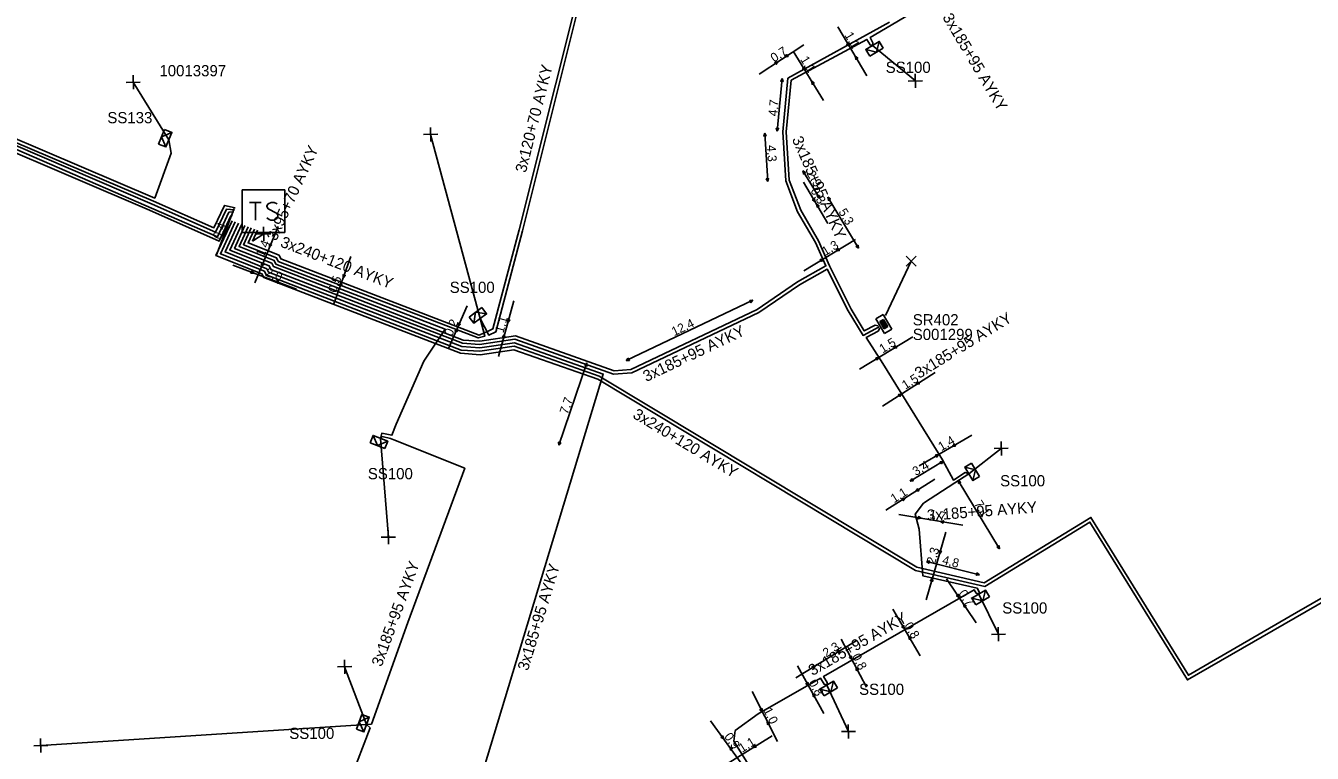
# Model space of a CAD drawing. Extents: x -762500 to -761285, y -1155006 to -1154135.
# Drawn here: x -762023.9 to -761909.8, y -1154863.6 to -1154799 of the extents above; entities that cross this region are included whole.
import ezdxf

# ---------------------------------------------------------------- set-up
doc = ezdxf.new("R2010")
doc.units = 0
for name, color, linetype in [('Vrstva 25', 7, 'Continuous'), ('Vrstva 26', 7, 'Continuous'), ('Vrstva 28', 7, 'Continuous'), ('Vrstva 29', 7, 'Continuous'), ('Vrstva 30', 7, 'Continuous'), ('Vrstva 31', 7, 'Continuous'), ('Vrstva 33', 7, 'Continuous'), ('Vrstva 34', 7, 'Continuous'), ('Vrstva 40', 7, 'Continuous'), ('Vrstva 5', 7, 'Continuous'), ('Vrstva 59', 7, 'Continuous'), ('Vrstva 6', 7, 'Continuous')]:
    doc.layers.add(name, color=color, linetype=linetype)

msp = doc.modelspace()

# ---------------------------------------------------------------- linework, layer by layer
at = {"layer": 'Vrstva 25'}
for points in [[(-762004.71, -1154813.561), (-762000.93, -1154813.561)], [(-762004.71, -1154817.34), (-762004.71, -1154813.561)], [(-762000.93, -1154813.561), (-762000.93, -1154817.34)], [(-762004.08, -1154814.663), (-762003.041, -1154814.663)], [(-762003.545, -1154814.663), (-762003.545, -1154816.237)], [(-762001.623, -1154814.789), (-762001.875, -1154814.663), (-762002.159, -1154814.663), (-762002.411, -1154814.789), (-762002.537, -1154814.978), (-762002.537, -1154815.041), (-762002.411, -1154815.23), (-762001.686, -1154815.607), (-762001.56, -1154815.766), (-762001.56, -1154815.923), (-762001.686, -1154816.111), (-762001.907, -1154816.237), (-762002.19, -1154816.237), (-762002.316, -1154816.175), (-762002.537, -1154816.049)], [(-762000.93, -1154817.34), (-762004.71, -1154817.34)]]:
    msp.add_lwpolyline(points, dxfattribs=at)
at = {"layer": 'Vrstva 28'}
for points in [[(-761947.857, -1154824.621), (-761948.5, -1154825.008)], [(-761948.5, -1154825.008), (-761947.727, -1154826.293)], [(-761947.821, -1154825.048), (-761948.145, -1154825.242)], [(-761948.145, -1154825.242), (-761947.762, -1154825.88)], [(-761947.837, -1154825.112), (-761948.08, -1154825.258)], [(-761948.08, -1154825.258), (-761947.746, -1154825.815)], [(-761947.854, -1154825.177), (-761948.016, -1154825.275)], [(-761948.016, -1154825.275), (-761947.73, -1154825.75)], [(-761947.87, -1154825.242), (-761947.951, -1154825.291)], [(-761947.951, -1154825.291), (-761947.713, -1154825.686)], [(-761947.694, -1154825.626), (-761947.889, -1154825.302)], [(-761947.633, -1154825.637), (-761947.87, -1154825.242)], [(-761947.084, -1154825.907), (-761947.857, -1154824.621)], [(-761947.568, -1154825.653), (-761947.854, -1154825.177)], [(-761947.503, -1154825.669), (-761947.837, -1154825.112)], [(-761947.438, -1154825.685), (-761947.821, -1154825.048)], [(-761947.762, -1154825.88), (-761947.438, -1154825.685)], [(-761947.746, -1154825.815), (-761947.503, -1154825.669)], [(-761947.73, -1154825.75), (-761947.568, -1154825.653)], [(-761947.727, -1154826.293), (-761947.084, -1154825.907)], [(-761947.713, -1154825.686), (-761947.633, -1154825.637)]]:
    msp.add_lwpolyline(points, dxfattribs=at)
at = {"layer": 'Vrstva 31'}
for points in [[(-761949.042, -1154801.692), (-761949.402, -1154801.092), (-761948.202, -1154800.371), (-761947.842, -1154800.971)], [(-761948.442, -1154801.331), (-761948.202, -1154800.371)], [(-761948.442, -1154801.331), (-761949.402, -1154801.092)], [(-761949.042, -1154801.692), (-761947.842, -1154800.971)], [(-762011.606, -1154808.186), (-762012.131, -1154809.484)], [(-762011.606, -1154808.186), (-762010.957, -1154808.448), (-762011.482, -1154809.746), (-762012.131, -1154809.484)], [(-762011.868, -1154808.835), (-762010.957, -1154808.448)], [(-762011.868, -1154808.835), (-762011.482, -1154809.746)], [(-761983.46, -1154823.998), (-761984.578, -1154824.84)], [(-761983.46, -1154823.998), (-761983.039, -1154824.557), (-761984.157, -1154825.399), (-761984.578, -1154824.84)], [(-761984.019, -1154824.419), (-761984.157, -1154825.399)], [(-761984.019, -1154824.419), (-761983.039, -1154824.557)], [(-761993.364, -1154835.996), (-761993.102, -1154835.347), (-761991.804, -1154835.872), (-761992.066, -1154836.521)], [(-761992.715, -1154836.258), (-761993.102, -1154835.347)], [(-761993.364, -1154835.996), (-761992.066, -1154836.521)], [(-761992.715, -1154836.258), (-761991.804, -1154835.872)], [(-761939.298, -1154839.002), (-761939.898, -1154839.363), (-761940.619, -1154838.163), (-761940.019, -1154837.802)], [(-761939.298, -1154839.002), (-761940.019, -1154837.802)], [(-761939.658, -1154838.402), (-761940.619, -1154838.163)], [(-761939.658, -1154838.402), (-761939.898, -1154839.363)], [(-761939.621, -1154850.392), (-761939.982, -1154849.792), (-761938.782, -1154849.071), (-761938.421, -1154849.671)], [(-761939.021, -1154850.032), (-761938.782, -1154849.071)], [(-761939.021, -1154850.032), (-761939.982, -1154849.792)], [(-761939.621, -1154850.392), (-761938.421, -1154849.671)], [(-761953.102, -1154858.473), (-761953.462, -1154857.873), (-761952.262, -1154857.152), (-761951.902, -1154857.752)], [(-761952.502, -1154858.112), (-761952.262, -1154857.152)], [(-761952.502, -1154858.112), (-761953.462, -1154857.873)], [(-761953.102, -1154858.473), (-761951.902, -1154857.752)], [(-761994.097, -1154860.11), (-761994.576, -1154861.426)], [(-761994.097, -1154860.11), (-761993.44, -1154860.35), (-761993.918, -1154861.665), (-761994.576, -1154861.426)], [(-761994.337, -1154860.768), (-761993.44, -1154860.35)], [(-761994.337, -1154860.768), (-761993.918, -1154861.665)]]:
    msp.add_lwpolyline(points, dxfattribs=at)
at = {"layer": 'Vrstva 34'}
for points in [[(-762014.369, -1154804.625), (-762014.391, -1154803.375)], [(-761944.989, -1154804.505), (-761945.011, -1154803.255)], [(-762015.005, -1154804.011), (-762013.755, -1154803.989)], [(-761945.625, -1154803.891), (-761944.375, -1154803.869)], [(-761987.989, -1154809.255), (-761988.011, -1154808.005)], [(-761988.625, -1154808.641), (-761987.375, -1154808.619)], [(-762003.435, -1154817.471), (-762002.185, -1154817.449)], [(-762002.799, -1154818.085), (-762002.821, -1154816.835)], [(-761945.822, -1154819.438), (-761944.938, -1154820.322)], [(-761945.822, -1154820.322), (-761944.938, -1154819.438)], [(-761938.005, -1154836.511), (-761936.755, -1154836.489)], [(-761937.369, -1154837.125), (-761937.391, -1154835.875)], [(-761991.739, -1154845.005), (-761991.761, -1154843.755)], [(-761992.375, -1154844.391), (-761991.125, -1154844.369)], [(-761937.619, -1154853.625), (-761937.641, -1154852.375)], [(-761938.255, -1154853.011), (-761937.005, -1154852.989)], [(-761996.255, -1154855.891), (-761995.005, -1154855.869)], [(-761995.619, -1154856.505), (-761995.641, -1154855.255)], [(-761951.565, -1154861.641), (-761950.315, -1154861.619)], [(-761950.929, -1154862.255), (-761950.951, -1154861.005)], [(-762023.215, -1154862.891), (-762021.965, -1154862.869)], [(-762022.579, -1154863.505), (-762022.601, -1154862.255)]]:
    msp.add_lwpolyline(points, dxfattribs=at)
at = {"layer": 'Vrstva 40'}
for points in [[(-761949.31, -1154803.42), (-761951.89, -1154799.07)], [(-761958.86, -1154803.28), (-761954.9, -1154800.67)], [(-761953.16, -1154805.62), (-761955.83, -1154801.23)], [(-761957.26, -1154808.34), (-761956.82, -1154803.68)], [(-761958.1, -1154812.82), (-761958.36, -1154808.51)], [(-761954.97, -1154811.87), (-761953.47, -1154814.32)], [(-761952.75, -1154816.54), (-761954.91, -1154812.87)], [(-762007, -1154819.32), (-762005.42, -1154815.2)], [(-761950.04, -1154818.73), (-761952.76, -1154814.21)], [(-762003.6, -1154821.81), (-762001.54, -1154816.79)], [(-761954.88, -1154820.73), (-761950.31, -1154817.95)], [(-761995.07, -1154819.47), (-761996.59, -1154823.67)], [(-762005.54, -1154820.23), (-761999.9, -1154822.37)], [(-761986.46, -1154827.7), (-761984.76, -1154823.86)], [(-761981.99, -1154828.33), (-761980.61, -1154823.39)], [(-761959.41, -1154823.35), (-761970.64, -1154828.7)], [(-761949.95, -1154829.47), (-761945.22, -1154826.59)], [(-761976.64, -1154836.22), (-761974.13, -1154828.92)], [(-761947.91, -1154832.74), (-761943.23, -1154829.75)], [(-761944.67, -1154838.06), (-761939.98, -1154835.32)], [(-761942.53, -1154837.64), (-761945.45, -1154839.41)], [(-761943.26, -1154839.23), (-761947.61, -1154841.98)], [(-761937.53, -1154845.41), (-761941.21, -1154839.35)], [(-761946.47, -1154842.37), (-761940.8, -1154843.32)], [(-761944.05, -1154849.95), (-761942.31, -1154843.93)], [(-761939.32, -1154847.72), (-761944.02, -1154846.53)], [(-761942.24, -1154848.08), (-761939.6, -1154851.98)], [(-761946.99, -1154850.78), (-761944.57, -1154854.9)], [(-761955.59, -1154856.86), (-761950.24, -1154853.58)], [(-761951.57, -1154853.45), (-761949.33, -1154857.71)], [(-761955.46, -1154855.8), (-761953.12, -1154860.02)], [(-761959.48, -1154858.09), (-761957.24, -1154862.52)], [(-761963.18, -1154860.67), (-761960.29, -1154864.64)], [(-761962.07, -1154864.73), (-761957.71, -1154862.01)]]:
    msp.add_lwpolyline(points, dxfattribs=at)
for points in [[(-761956.572, -1154801.771), (-761956.425, -1154801.546), (-761956.308, -1154801.719)], [(-761950.869, -1154800.792), (-761951.087, -1154800.633), (-761950.907, -1154800.525)], [(-761957.188, -1154802.179), (-761957.336, -1154802.405), (-761957.453, -1154802.231)], [(-761954.789, -1154802.942), (-761955.009, -1154802.787), (-761954.832, -1154802.676)], [(-761950.331, -1154801.698), (-761950.113, -1154801.857), (-761950.293, -1154801.965)], [(-761956.82, -1154803.677), (-761956.737, -1154803.934), (-761956.945, -1154803.916)], [(-761954.201, -1154803.908), (-761953.981, -1154804.063), (-761954.158, -1154804.174)], [(-761957.26, -1154808.342), (-761957.343, -1154808.085), (-761957.135, -1154808.104)], [(-761958.36, -1154808.507), (-761958.238, -1154808.748), (-761958.447, -1154808.763)], [(-761958.1, -1154812.822), (-761958.221, -1154812.582), (-761958.013, -1154812.567)], [(-761954.971, -1154811.868), (-761954.751, -1154812.024), (-761954.928, -1154812.134)], [(-761953.469, -1154814.323), (-761953.69, -1154814.167), (-761953.512, -1154814.056)], [(-761953.898, -1154814.602), (-761954.116, -1154814.443), (-761953.937, -1154814.335)], [(-761953.762, -1154814.818), (-761953.544, -1154814.977), (-761953.723, -1154815.085)], [(-761952.761, -1154814.207), (-761952.541, -1154814.363), (-761952.718, -1154814.474)], [(-762006.289, -1154817.448), (-762006.276, -1154817.717), (-762006.472, -1154817.646)], [(-762006.141, -1154817.073), (-762006.154, -1154816.803), (-762005.957, -1154816.875)], [(-762002.301, -1154818.642), (-762002.305, -1154818.373), (-762002.111, -1154818.451)], [(-761950.039, -1154818.733), (-761950.26, -1154818.577), (-761950.082, -1154818.466)], [(-761953.168, -1154819.689), (-761953.323, -1154819.909), (-761953.434, -1154819.732)], [(-761952.022, -1154818.991), (-761951.867, -1154818.771), (-761951.756, -1154818.948)], [(-762003.667, -1154820.941), (-762003.937, -1154820.954), (-762003.865, -1154820.758)], [(-762002.839, -1154819.958), (-762002.835, -1154820.227), (-762003.029, -1154820.149)], [(-762001.772, -1154821.659), (-762001.503, -1154821.646), (-762001.574, -1154821.842)], [(-761995.909, -1154821.788), (-761995.891, -1154822.057), (-761996.089, -1154821.989)], [(-761995.751, -1154821.352), (-761995.769, -1154821.083), (-761995.571, -1154821.151)], [(-761959.407, -1154823.349), (-761959.585, -1154823.552), (-761959.676, -1154823.364)], [(-761985.571, -1154825.692), (-761985.57, -1154825.423), (-761985.378, -1154825.504)], [(-761981.151, -1154825.322), (-761981.187, -1154825.055), (-761980.985, -1154825.109)], [(-761985.649, -1154825.868), (-761985.65, -1154826.137), (-761985.842, -1154826.056)], [(-761981.449, -1154826.397), (-761981.413, -1154826.664), (-761981.615, -1154826.61)], [(-761946.932, -1154827.631), (-761946.777, -1154827.411), (-761946.666, -1154827.588)], [(-761974.129, -1154828.917), (-761974.107, -1154829.186), (-761974.305, -1154829.121)], [(-761970.642, -1154828.701), (-761970.464, -1154828.498), (-761970.373, -1154828.686)], [(-761948.238, -1154828.429), (-761948.393, -1154828.649), (-761948.504, -1154828.472)], [(-761944.922, -1154830.831), (-761944.771, -1154830.608), (-761944.657, -1154830.783)], [(-761946.218, -1154831.659), (-761946.369, -1154831.882), (-761946.483, -1154831.707)], [(-761976.641, -1154836.223), (-761976.664, -1154835.954), (-761976.465, -1154836.019)], [(-761941.712, -1154836.331), (-761941.553, -1154836.113), (-761941.445, -1154836.293)], [(-761942.938, -1154837.049), (-761943.097, -1154837.267), (-761943.205, -1154837.087)], [(-761942.528, -1154837.639), (-761942.683, -1154837.86), (-761942.794, -1154837.682)], [(-761945.452, -1154839.411), (-761945.297, -1154839.191), (-761945.186, -1154839.368)], [(-761944.953, -1154840.301), (-761944.801, -1154840.078), (-761944.687, -1154840.254)], [(-761941.211, -1154839.347), (-761940.991, -1154839.503), (-761941.168, -1154839.614)], [(-761945.917, -1154840.909), (-761946.069, -1154841.132), (-761946.183, -1154840.957)], [(-761944.497, -1154842.7), (-761944.759, -1154842.764), (-761944.726, -1154842.558)], [(-761942.773, -1154842.989), (-761942.511, -1154842.925), (-761942.544, -1154843.131)], [(-761942.861, -1154845.852), (-761942.893, -1154845.585), (-761942.692, -1154845.642)], [(-761937.529, -1154845.412), (-761937.749, -1154845.256), (-761937.572, -1154845.146)], [(-761944.023, -1154846.529), (-761943.756, -1154846.488), (-761943.807, -1154846.691)], [(-761943.489, -1154848.028), (-761943.457, -1154848.295), (-761943.658, -1154848.238)], [(-761939.318, -1154847.721), (-761939.584, -1154847.762), (-761939.534, -1154847.559)], [(-761941.119, -1154849.732), (-761941.347, -1154849.589), (-761941.176, -1154849.469)], [(-761940.721, -1154850.318), (-761940.493, -1154850.462), (-761940.664, -1154850.581)], [(-761945.979, -1154852.502), (-761946.197, -1154852.343), (-761946.017, -1154852.235)], [(-761945.581, -1154853.178), (-761945.363, -1154853.337), (-761945.543, -1154853.445)], [(-761951.953, -1154854.631), (-761951.797, -1154854.411), (-761951.687, -1154854.588)], [(-761950.639, -1154855.222), (-761950.848, -1154855.052), (-761950.663, -1154854.954)], [(-761953.888, -1154855.819), (-761954.044, -1154856.039), (-761954.154, -1154855.862)], [(-761950.261, -1154855.938), (-761950.052, -1154856.108), (-761950.237, -1154856.206)], [(-761954.489, -1154857.552), (-761954.704, -1154857.389), (-761954.523, -1154857.285)], [(-761954.091, -1154858.268), (-761953.876, -1154858.431), (-761954.057, -1154858.535)], [(-761958.579, -1154859.872), (-761958.785, -1154859.698), (-761958.599, -1154859.603)], [(-761958.141, -1154860.738), (-761957.935, -1154860.912), (-761958.121, -1154861.007)], [(-761961.999, -1154862.292), (-761962.232, -1154862.156), (-761962.065, -1154862.031)], [(-761961.472, -1154863.018), (-761961.238, -1154863.154), (-761961.405, -1154863.28)], [(-761959.412, -1154863.071), (-761959.261, -1154862.848), (-761959.147, -1154863.023)]]:
    msp.add_lwpolyline(points, close=True, dxfattribs=at)
at = {"layer": 'Vrstva 5'}
for points in [[(-762005.47, -1154815.51), (-762005.9, -1154815.54), (-762006.91, -1154817.72), (-762027.5, -1154808.79), (-762050.51, -1154798.85), (-762079.21, -1154786.89), (-762094.1, -1154780.44), (-762101.63, -1154777.4), (-762108.5, -1154774.39), (-762121.62, -1154768.73), (-762128.38, -1154765.83), (-762137.12, -1154763.24), (-762132.4, -1154742.15), (-762126.9, -1154716.57), (-762123.43, -1154700.6), (-762123.89, -1154700.17)], [(-761945.21, -1154725.4), (-761946.29, -1154728.22), (-761948.73, -1154735.39), (-761953.32, -1154752.86), (-761953.98, -1154753.7), (-761954.88, -1154757.18), (-761961.57, -1154755.63), (-761964.09, -1154754.7), (-761966.98, -1154765.99), (-761970.2, -1154778.58), (-761979.86, -1154817.19), (-761982.22, -1154826.16), (-761982.85, -1154826.44), (-761983.6, -1154824.98), (-761983.19, -1154826.55), (-761983.78, -1154826.69), (-762001.52, -1154819.9), (-762001.67, -1154819.6), (-762004.6, -1154818.43), (-762003.91, -1154816.93)], [(-761967.13, -1154735.43), (-761966.83, -1154735.04), (-761966.07, -1154732.22), (-761958.94, -1154733.93), (-761964.38, -1154754.62), (-761966.99, -1154764.58), (-761970.46, -1154778.33), (-761980.15, -1154817.11), (-761982.47, -1154825.89), (-761983.01, -1154826.14), (-761983.31, -1154826.27), (-761983.69, -1154826.44), (-762001.3, -1154819.66), (-762001.45, -1154819.36), (-762004.19, -1154818.26), (-762003.63, -1154817.03)], [(-761793.37, -1154751.76), (-761793.05, -1154752.07), (-761787.15, -1154762.31), (-761806.36, -1154782.09), (-761826.62, -1154799.89), (-761862.11, -1154822.83), (-761911.18, -1154851.08), (-761920.77, -1154856.64), (-761929.42, -1154842.63), (-761938.89, -1154848.44), (-761944.86, -1154847.05), (-761973.05, -1154830.1), (-761980.58, -1154827.44), (-761983.64, -1154827.88), (-761985.29, -1154827.77), (-762002.6, -1154821.09), (-762002.75, -1154820.78), (-762006.65, -1154819.22), (-762005.33, -1154816.4)], [(-762093.99, -1154780.16), (-762079.09, -1154786.61), (-762062.62, -1154793.49), (-762050.39, -1154798.57), (-762036.07, -1154804.84), (-762027.38, -1154808.52), (-762012.7, -1154814.81), (-762007.08, -1154817.32), (-762006.12, -1154815.27), (-762005.4, -1154815.32)], [(-761948.29, -1154825.61), (-761948.57, -1154825.55), (-761949.54, -1154826.07), (-761950.7, -1154824.14), (-761952.61, -1154820.31), (-761953.6, -1154818.08), (-761955.16, -1154815.36), (-761956.19, -1154812.68), (-761956.45, -1154808.4), (-761956.02, -1154803.83), (-761949.29, -1154800.2), (-761949.02, -1154800.67), (-761948.8, -1154800.73), (-761948.76, -1154800.5), (-761949.01, -1154800.04), (-761947.14, -1154798.94), (-761936.16, -1154792.41), (-761935.97, -1154792.88), (-761935.78, -1154792.92)], [(-762005.59, -1154815.82), (-762005.72, -1154815.85), (-762006.76, -1154818.1), (-762012.94, -1154815.36), (-762033.69, -1154806.48), (-762050.63, -1154799.12), (-762054.86, -1154809.84), (-762055.91, -1154809.39), (-762056.11, -1154809.45)], [(-761947.3, -1154798.68), (-761956.3, -1154803.65), (-761956.75, -1154808.4), (-761956.49, -1154812.74), (-761955.44, -1154815.49), (-761953.86, -1154818.22), (-761952.94, -1154820.31), (-761955.44, -1154821.73), (-761959.04, -1154824.17), (-761970.23, -1154829.5), (-761971.73, -1154829.62), (-761980.47, -1154826.52), (-761983.65, -1154826.98), (-761985.1, -1154826.88), (-762001.95, -1154820.37), (-762002.1, -1154820.07), (-762005.39, -1154818.75), (-762004.47, -1154816.72)], [(-762035.91, -1154804.22), (-762035.75, -1154804.69), (-762012.6, -1154814.56), (-762007.23, -1154816.91), (-762006.3, -1154814.93), (-762005.33, -1154815.14)], [(-762035.91, -1154804.22), (-762035.47, -1154804.46), (-762012.48, -1154814.28), (-762011.03, -1154810.29), (-762011.22, -1154809.1)], [(-762005.61, -1154816.29), (-762007.05, -1154819.38), (-762002.97, -1154821.02), (-762002.81, -1154821.33), (-761985.36, -1154828.06), (-761983.62, -1154828.19), (-761980.61, -1154827.74), (-761973.18, -1154830.37), (-761944.98, -1154847.33), (-761938.84, -1154848.76), (-761929.52, -1154843.04), (-761920.87, -1154857.05), (-761881.47, -1154834.36), (-761875.67, -1154843.65), (-761885.32, -1154849.18), (-761880.3, -1154857.9), (-761880.08, -1154858.31)], [(-761983.32, -1154866.37), (-761983.65, -1154866.06), (-761972.68, -1154829.91), (-761980.55, -1154827.13), (-761983.65, -1154827.58), (-761985.23, -1154827.47), (-762002.38, -1154820.85), (-762002.54, -1154820.55), (-762006.24, -1154819.06), (-762005.04, -1154816.5)], [(-761948.22, -1154825.72), (-761949.64, -1154826.47), (-761950.96, -1154824.28), (-761952.83, -1154820.59), (-761955.28, -1154821.99), (-761958.89, -1154824.43), (-761970.15, -1154829.8), (-761971.77, -1154829.92), (-761980.52, -1154826.82), (-761983.66, -1154827.28), (-761985.16, -1154827.17), (-762002.17, -1154820.61), (-762002.32, -1154820.31), (-762005.81, -1154818.92), (-762004.75, -1154816.61)], [(-762004.19, -1154816.82), (-762005, -1154818.59), (-762001.88, -1154819.83), (-762001.73, -1154820.14), (-761986.7, -1154825.92), (-761988.6, -1154828.76), (-761991.05, -1154834.36), (-761991.43, -1154835.33), (-761992.34, -1154835.15), (-761992.45, -1154835.61)], [(-762003.35, -1154817.14), (-762003.79, -1154818.1)], [(-761948.16, -1154825.83), (-761948.3, -1154826.1), (-761949.36, -1154826.66), (-761947.89, -1154828.97), (-761942.6, -1154837.53), (-761941.63, -1154839.32), (-761940.58, -1154838.63), (-761940.26, -1154838.76), (-761941.49, -1154839.57), (-761944.27, -1154841.37), (-761945.01, -1154842.35), (-761944.66, -1154843.67), (-761944.34, -1154847.8), (-761939.51, -1154848.91), (-761939.34, -1154849.22), (-761939.38, -1154849.43), (-761939.6, -1154849.34), (-761939.77, -1154849.07), (-761953.14, -1154856.74), (-761952.83, -1154857.28), (-761952.86, -1154857.51), (-761953.09, -1154857.42), (-761953.4, -1154856.9), (-761958.94, -1154860.07), (-761960.99, -1154861.55), (-761961.1, -1154862.5), (-761956.88, -1154869.27)], [(-761995.1, -1154865.87), (-761993.37, -1154861.3), (-761993.68, -1154861.01), (-761993.25, -1154860.97), (-761990.01, -1154851.95), (-761984.98, -1154838.27), (-761991.27, -1154835.73), (-761991.55, -1154835.61), (-761992.3, -1154835.46), (-761992.45, -1154835.61)]]:
    msp.add_lwpolyline(points, dxfattribs=at)
at = {"layer": 'Vrstva 59'}
for points in [[(-761948.8, -1154800.73), (-761945, -1154803.88)], [(-762011.22, -1154809.1), (-762014.38, -1154804)], [(-761983.6, -1154824.98), (-761988, -1154808.63)], [(-762003.79, -1154818.1), (-762002.81, -1154817.46)], [(-761947.66, -1154824.69), (-761945.38, -1154819.88)], [(-761992.45, -1154835.61), (-761991.75, -1154844.38)], [(-761940.26, -1154838.76), (-761937.38, -1154836.5)], [(-761939.38, -1154849.43), (-761937.63, -1154853)], [(-761993.68, -1154861.01), (-761995.63, -1154855.88)], [(-761952.86, -1154857.51), (-761950.94, -1154861.63)], [(-761993.68, -1154861.01), (-762022.59, -1154862.88)]]:
    msp.add_lwpolyline(points, dxfattribs=at)

# ---------------------------------------------------------------- texts
at = {"layer": 'Vrstva 26'}
msp.add_text('10013397', height=0.9943, dxfattribs=at).set_placement((-762012.06, -1154803.47))
at = {"layer": 'Vrstva 29'}
msp.add_text('S001299', height=0.9943, dxfattribs=at).set_placement((-761945.23, -1154826.88))
at = {"layer": 'Vrstva 30'}
msp.add_text('SR402', height=0.9943, dxfattribs=at).set_placement((-761945.23, -1154825.58))
at = {"layer": 'Vrstva 33'}
for s, p in [('SS100', (-761947.63, -1154803.17)), ('SS133', (-762016.68, -1154807.64)), ('SS100', (-761986.31, -1154822.7)), ('SS100', (-761993.57, -1154839.24)), ('SS100', (-761937.48, -1154839.87)), ('SS100', (-761937.29, -1154851.16)), ('SS100', (-761949.99, -1154858.38)), ('SS100', (-762000.54, -1154862.29))]:
    msp.add_text(s, height=0.9943, dxfattribs=at).set_placement(p)
at = {"layer": 'Vrstva 40'}
for s, rotation, p in [('1,1', 300.68549, (-761951.31, -1154799.82)), ('0,7', 33.4506, (-761957.52, -1154802.26)), ('1,1', 301.30978, (-761955.24, -1154801.97)), ('4,7', 84.60589, (-761957.26, -1154807.05)), ('4,3', 273.452, (-761958.17, -1154809.6)), ('2,9', 301.47705, (-761954.67, -1154812.13)), ('0,3', 300.49687, (-761954.33, -1154813.62)), ('5,3', 301.09437, (-761951.85, -1154815.5)), ('0,4', 69.0455, (-762006.63, -1154818.02)), ('1,4', 67.75149, (-762002.81, -1154819.58)), ('1,3', 31.32809, (-761952.99, -1154819.43)), ('2,0', 339.2454, (-762002.72, -1154821.17)), ('0,5', 70.01769, (-761996.39, -1154822.75)), ('0,2', 66.05106, (-761986.11, -1154826.61)), ('1,1', 74.37348, (-761981.55, -1154826.31)), ('12,4', 25.47311, (-761966.4, -1154826.55)), ('1,5', 31.41103, (-761947.9, -1154828.08)), ('1,5', 32.55897, (-761945.88, -1154831.3)), ('7,7', 71.05527, (-761975.84, -1154833.53)), ('1,4', 30.34448, (-761942.69, -1154836.76)), ('3,4', 31.08012, (-761944.96, -1154838.97)), ('1,1', 32.33499, (-761946.88, -1154841.38)), ('7,1', 301.26847, (-761939.82, -1154841.41)), ('1,7', 350.48211, (-761943.8, -1154842.7)), ('2,3', 73.88201, (-761943.27, -1154846.84)), ('4,8', 345.79176, (-761942.67, -1154846.75)), ('0,7', 304.13318, (-761941.22, -1154849.38)), ('0,8', 300.46582, (-761946.01, -1154852.21)), ('2,3', 31.52353, (-761952.91, -1154855.08)), ('0,8', 297.82595, (-761950.65, -1154854.95)), ('0,8', 299.05822, (-761954.5, -1154857.28)), ('1,0', 296.82824, (-761958.51, -1154859.74)), ('0,9', 306.13674, (-761962, -1154862.09)), ('1,1', 32.0062, (-761960.37, -1154863.53))]:
    msp.add_text(s, height=0.7954, rotation=rotation, dxfattribs=at).set_placement(p)
at = {"layer": 'Vrstva 6'}
for s, height, rotation, p in [('3x185+95 AYKY', 0.99429, 300.72997, (-761942.63, -1154798.23)), ('3x120+70 AYKY', 0.99429, 75.9721, (-761979.55, -1154812.09)), ('3x95+70 AYKY', 0.99429, 65.36293, (-762001.7, -1154818.15)), ('3x185+95 AYKY', 0.99429, 293.81671, (-761955.97, -1154809.05)), ('3x240+120 AYKY', 0.99429, 338.96651, (-762001.4, -1154818.57)), ('3x185+95 AYKY', 0.99429, 31.71796, (-761944.67, -1154830.34)), ('3x185+95 AYKY', 0.99429, 25.46848, (-761968.87, -1154830.62)), ('3x240+120 AYKY', 0.99429, 328.99176, (-761970.15, -1154833.74)), ('3x185+95 AYKY', 0.99428, 4.43053, (-761943.94, -1154842.94)), ('3x185+95 AYKY', 0.99429, 69.81203, (-761992.35, -1154855.94)), ('3x185+95 AYKY', 0.99429, 73.11697, (-761979.37, -1154856.3)), ('3x185+95 AYKY', 0.99429, 29.86057, (-761954.13, -1154856.72))]:
    msp.add_text(s, height=height, rotation=rotation, dxfattribs=at).set_placement(p)

doc.saveas('drawing.dxf')
